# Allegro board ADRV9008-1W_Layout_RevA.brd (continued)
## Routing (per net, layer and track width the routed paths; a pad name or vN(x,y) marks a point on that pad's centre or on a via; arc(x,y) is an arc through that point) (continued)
OUT12_N: length 7.2
  BOTTOM w0.203: R431.1 80.57,63.93 80.58,63.92 ; 80.58,63.92 80.05,63.92 79.76,64.21 R433.1 ; 80.58,63.92 82.17,63.92 82.62,63.48 82.62,61.79 82.85,61.56 83.47,61.56 83.54,61.63 U401.29
OUT13: length 3.9
  BOTTOM w0.203: 81.75,59.71 83.63,59.71 83.72,59.63 U401.25 ; 81.75,59.71 R434.1 ; 81.75,59.71 81.06,59.71 R436.1
OUT13_N: length 3.9
  BOTTOM w0.203: 81.75,60.07 81.06,60.07 R435.1 ; 81.75,60.07 R434.2 ; 81.75,60.07 83.62,60.07 83.68,60.13 U401.26
PWRSUPPLYENABLE: length 111.8
  TOP w0.305: v2(79.68,19.06) 79.66,19.07 R902.1
  L8_SIG w0.394: v4(140.3,60.87) 142.31,60.87 143.58,59.6 143.58,49.9 145.04,48.45 145.04,33.69 143.58,32.24 143.58,22.2 143.19,21.81 142.66,21.81 142.31,21.46 142.31,20.87 141.98,20.54 141.39,20.54 138.89,18.04 127.56,18.04 127.02,18.58 123.59,18.58 122.42,19.75 121.66,19.75 121.39,19.48 120.1,19.48 120.09,19.47 119.55,19.47 119.54,19.48 116.34,19.48 115.71,20.11 98.31,20.11 97.31,19.11 79.73,19.11 v2(79.68,19.06)
  BOTTOM w0.394: v4(140.3,60.87) 139.74,60.31 P801.D1
REF_CLK_IN+: length 62.9
  BOTTOM w0.203: R436.2 79.47,59.71 78.74,59.71 ; 78.74,59.71 77.41,59.71 ; 78.74,59.71 C445.2 ; 77.41,59.71 77.09,59.71 arc(72.18,59.25) 67.44,57.88 arc(67.04,57.73) 66.63,57.6 66.64,57.6 arc(58.87,55.89) 50.94,55.27 50.94,55.27 arc(47.52,53.86) 46.11,50.44 46.11,45.64 arc(44.94,42.82) 42.12,41.65 38.29,41.65 arc(35.41,41.03) 33.1,39.2 arc(32.44,38) 32.21,36.64 32.21,35.86 ; 77.41,59.71 L401.1 ; 32.21,35.86 32.21,35.59 arc(32.24,35.42) C103.1 ; 32.21,35.86 R121.1
REF_CLK_IN-: length 63.5
  BOTTOM w0.203: R121.2 31.85,35.86 ; 31.85,35.86 31.85,36.64 arc(32.1,38.12) 32.83,39.43 arc(35.26,41.35) 38.29,42 42.12,42 arc(44.69,43.07) 45.75,45.64 45.75,50.44 arc(47.27,54.11) 50.94,55.62 arc(58.82,56.24) 66.54,57.94 arc(66.93,58.06) 67.31,58.21 arc(72.11,59.6) 77.09,60.07 77.41,60.07 ; 31.85,35.86 31.85,35.59 arc(31.81,35.42) C104.1 ; L401.2 77.41,60.07 ; 77.41,60.07 78.74,60.07 ; 78.74,60.07 79.47,60.07 R435.2 ; 78.74,60.07 C445.1
RESETB: length 120
  TOP w0.254: U101.J4 v1(35.64,31.68)
  TOP w0.394: TP803.1 128.99,48.07 129.42,48.5 R804.1
  L5_SIG w0.114: TP803.1 123.68,48.07 120.46,51.28 114.81,51.28 113.92,52.17 107.63,52.17 101.89,46.43 88.74,46.43 88.39,46.07 78.35,46.07 76.2,43.92 74.93,43.92 73.51,42.5 73.08,42.5 72.43,41.85 72.43,41.29 68.6,37.46 51.1,37.46 48.34,40.22 v5(40.9,40.22) 40.83,40.22 39.89,39.28 38.65,39.28 38.44,39.08 38.44,35.52 39.23,34.74 39.23,33.92 39.22,33.91 39.22,32.34 39,32.11 38.74,32.11 38.44,31.81 38.44,31.53 38.14,31.23 36.08,31.23 v1(35.64,31.68)
  BOTTOM w0.305: R110.2 40.16,38.61 40.9,39.35 v5(40.9,40.22)
RF_EXT_LO+: length 5.8
  TOP w0.203: U101.B8 v1(29.24,34.88)
  L10_SIG w0.254: v1(29.24,34.88) 29.24,34.58 28.89,34.24 27.98,34.24 27.83,34.09 25.47,34.09 v5(25.19,34.37)
  BOTTOM w0.203: C304.2 v5(25.19,34.37)
RF_EXT_LO-: length 5.8
  TOP w0.203: U101.B7 v1(29.24,33.28)
  L10_SIG w0.254: v5(25.19,33.45) 25.47,33.73 27.97,33.73 28.13,33.89 28.96,33.89 29.24,33.61 v1(29.24,33.28)
  BOTTOM w0.203: C305.2 v5(25.19,33.45)
RF_SYNTH_VTUNE: length 29.9
  TOP w0.203: C136.1 56.46,41.45 P104.5
  TOP w0.254: v5(34.04,35.68) U101.G9
  L7_SIG w0.114: v5(34.04,35.68) 34.42,36.06 34.42,38.13 34.83,38.54 34.98,38.54 35.18,38.74 35.18,38.9 35.56,39.28 42.99,39.28 44.9,41.19 46.99,41.19 48.33,42.52 51.95,42.52 52.13,42.34 53.24,42.34 53.48,42.58 55.18,42.58 P104.5
RX1_BAL+: length 3.3
  TOP w0.127: 18.86,38.89 T201.5
  TOP w0.203: 20.46,39.24 20.84,39.24 arc(21.2,39.17) R205.1 ; 20.46,39.24 19.85,39.24 arc(19.32,39.15) 18.86,38.89 arc(18.8,38.84) T201.5 ; 20.46,39.24 C204.1
RX1_BAL-: length 3.1
  TOP w0.203: 20.46,39.6 20.84,39.6 arc(21.2,39.67) R206.1 ; 20.46,39.6 C204.2 ; 20.46,39.6 19.84,39.6 arc(19.25,39.71) T201.4
RX1_ENABLE: length 37
  TOP w0.254: U101.M5 v1(38.04,31.68)
  TOP w0.305: R117.1 53.91,41.44 P104.7
  L5_SIG w0.114: P104.7 53.34,41.38 49.86,44.86 40.25,44.86 39.49,44.1 38.35,44.1 35.3,41.05 35.3,34.21 36.06,33.46 36.06,33.14 36.38,32.81 36.58,32.81 36.77,32.62 36.77,32.42 37.15,32.04 37.67,32.04 v1(38.04,31.68)
  BOTTOM w0.203: R839.1 P104.7
RX1_IN+: length 8.4
  TOP w0.203: U101.A9 28.7,35.41 arc(28.58,35.49) 28.44,35.52 arc(27.72,35.68) 27.12,36.11 25.16,38.34 arc(24.28,39) 23.21,39.24 ; 23.21,39.24 23.2,39.24 C207.1 ; 23.21,39.24 arc(23.12,39.24) 23.02,39.24 arc(22.56,39.17) R205.2
RX1_IN-: length 8.4
  TOP w0.203: 23.22,39.6 23.2,39.6 C207.2 ; 23.22,39.6 arc(23.11,39.6) 23.01,39.6 arc(22.55,39.66) R206.2 ; 23.22,39.6 arc(24.43,39.32) 25.42,38.58 27.39,36.35 arc(27.86,36) 28.44,35.88 28.5,35.88 arc(28.63,35.9) 28.74,35.98 U101.A10
RX1_UNBAL: length 2.2
  TOP w0.203: C248.1 13.11,40.1
  TOP w0.394: R202.2 C203.1 12.51,40.61 arc(12.65,40.48) 12.79,40.34 arc(12.95,40.22) 13.11,40.1
RX2_BAL+: length 3.6
  TOP w0.127: T202.5 19.12,29.57
  TOP w0.203: 20.46,29.75 19.85,29.75 arc(19.47,29.7) 19.12,29.57 arc(18.92,29.44) T202.5 ; 20.46,29.75 C211.1 ; 20.46,29.75 20.84,29.75 arc(21.2,29.67) R212.1
RX2_BAL-: length 3.1
  TOP w0.203: 20.46,30.1 19.84,30.1 arc(19.25,30.22) T202.4 ; 20.46,30.1 C211.2 ; 20.46,30.1 20.84,30.1 arc(21.2,30.17) R213.1
RX2_ENABLE: length 31.3
  TOP w0.254: U101.M7 v1(38.04,34.08)
  TOP w0.305: R116.1 53.91,38.77 P104.8
  L5_SIG w0.114: P104.8 52.58,40.11 50.93,40.11 48.19,42.85 43.44,42.85 43.05,42.45 38.6,42.45 36.84,40.69 36.84,35.53 37.08,35.29 37.37,35.29 37.66,35 37.66,34.46 v1(38.04,34.08)
  BOTTOM w0.203: R842.1 P104.8
RX2_IN+: length 7.6
  TOP w0.203: 23.21,29.74 23.02,29.75 arc(22.56,29.69) R212.2 ; 23.21,29.74 C214.1 ; 23.21,29.74 arc(23.98,29.85) 24.7,30.16 arc(25.8,30.85) 26.84,31.61 arc(27.61,32.06) 28.47,32.28 arc(28.69,32.23) U101.A5
RX2_IN-: length 7.7
  TOP w0.203: 23.19,30.1 23.02,30.1 arc(22.56,30.17) R213.2 ; 23.19,30.1 arc(23.2,30.17) C214.2 ; 23.19,30.1 arc(23.88,30.19) 24.52,30.47 arc(25.59,31.14) 26.62,31.89 arc(27.47,32.39) 28.44,32.63 arc(28.58,32.66) 28.7,32.74 U101.A6
RX2_UNBAL: length 4.1
  TOP w0.203: C249.1 12.96,30.56
  TOP w0.394: R209.2 C210.1 10.78,29.45 arc(11.1,30.23) 11.88,30.56 12.96,30.56
SERDOUT0+: length 3
  BOTTOM w0.203: P801.A2 143.55,58.42 arc(143.61,58.28) 143.75,58.22 145.7,58.22 arc(145.87,58.25) 146.02,58.35 C105.1
SERDOUT0-: length 3
  BOTTOM w0.203: P801.A3 143.55,57.66 arc(143.61,57.8) 143.75,57.86 145.7,57.86 arc(145.87,57.83) 146.02,57.73 C106.1
SERDOUT1+: length 3
  BOTTOM w0.203: P801.A6 143.55,53.34 arc(143.61,53.2) 143.75,53.14 145.7,53.14 arc(145.87,53.17) 146.02,53.27 C107.1
SERDOUT1-: length 3
  BOTTOM w0.203: C108.1 146.02,52.65 arc(145.87,52.75) 145.7,52.78 143.75,52.78 arc(143.61,52.72) 143.55,52.58 P801.A7
SERDOUT2+: length 1.4
  TOP w0.203: v4(141.67,52.95) 141.67,52.93 C109.1
  BOTTOM w0.203: v4(141.67,52.95) 141.66,52.95 P801.C6
SERDOUT2-: length 1.4
  TOP w0.203: v4(141.64,51.69) C110.1
  BOTTOM w0.203: v4(141.64,51.69) P801.C7
SERDOUT3+: length 3
  BOTTOM w0.203: P801.A10 143.55,48.26 arc(143.61,48.12) 143.75,48.06 145.7,48.06 arc(145.87,48.09) 146.02,48.19 C111.1
SERDOUT3-: length 3
  BOTTOM w0.203: P801.A11 143.55,47.5 arc(143.61,47.64) 143.75,47.7 145.7,47.7 arc(145.87,47.67) 146.02,47.57 C112.1
SPI_CLK: length 112.9
  TOP w0.254: U403.3 120.14,47.94 121.68,46.4 121.68,44.26 TP805.1 ; U101.K9 v1(36.44,35.68)
  TOP w0.305: R806.1 131.17,43.47 129.64,41.95 121.6,41.95 TP805.1
  L7_SIG w0.114: v3(89.47,45.89) 89.79,46.2 100.9,46.2 105.16,41.95 119.37,41.95 TP805.1
  L8_SIG w0.114: v1(36.44,35.68) 36.69,35.68 37.08,35.29 41.54,35.29 43.18,36.93 45.21,36.93 51.69,43.41 70.36,43.41 72.39,45.44 77.09,45.44 77.72,46.07 89.29,46.07 v3(89.47,45.89)
SPI_CLK_9528: length 43.5
  TOP w0.203: U403.12 v2(120.14,53.63)
  L7_SIG w0.114: v2(120.14,53.63) 98.81,53.63 98.43,54.01 87.82,54.01 83.76,58.08 82.42,58.08 v2(82.21,58.29)
  BOTTOM w0.254: U401.22 83.47,58.13 83.38,58.04 82.46,58.04 v2(82.21,58.29)
SPI_CS0: length 119.8
  TOP w0.254: U101.K10 v1(36.44,36.48) ; v4(139.1,42.87) 138.89,42.87 138.55,42.53 R832.2 R846.1 ; TP816.1 119.9,45.99 118.65,47.24 117.33,47.24 116.71,47.86 U402.7
  L7_SIG w0.114: TP816.1 119.34,44.84 116.88,44.84 115,42.97 105.67,42.97 101.6,47.03 96.52,47.03 96.01,47.54 v3(88.2,47.54)
  L8_SIG w0.114: v3(88.2,47.54) 72.08,47.54 68.84,44.3 48.96,44.3 44.88,40.22 43.42,40.22 40.43,37.22 40.36,37.22 40.01,36.88 36.84,36.88 v1(36.44,36.48)
  L8_SIG w0.254: v4(139.1,42.87) 138.49,43.48 124.64,43.48 123.63,44.49 121.98,44.49 TP816.1
SPI_CS1: length 34.8
  TOP w0.254: 121.44,50.48 U403.5
  TOP w0.305: U402.1 120.6,51.32 121.44,50.48 122.03,51.08 123.99,51.08 TP815.1 130.59,49.7 130.74,49.86 134.53,49.86 135.89,48.49 135.89,47.6 136.27,47.22 136.74,47.22 137.12,46.84 137.12,40.05 137.5,39.67 138.21,39.67 138.55,40.01 R833.2 R847.1
SPI_CS_9528: length 46.6
  TOP w0.203: U403.10 v2(121.44,53.63)
  L7_SIG w0.114: v2(81.7,57.55) 83.33,57.55 87.31,53.58 87.4,53.58 87.6,53.38 98.05,53.38 98.68,52.74 103.63,52.74 104.14,52.24 105.03,52.24 105.54,52.74 114.81,52.74 115.06,53 120.8,53 v2(121.44,53.63)
  BOTTOM w0.254: U401.21 83.78,57.63 83.69,57.63 83.62,57.55 v2(81.7,57.55)
SPI_DIN: length 114.2
  TOP w0.254: U101.J9 v1(35.64,35.68) ; U403.4 120.79,48.18 123,45.96 TP806.1
  TOP w0.305: TP806.1 125.39,43.98 129.45,43.98 130.14,44.67 R807.1
  L7_SIG w0.114: TP806.1 122.03,47.33 117.4,47.33 113.93,43.86 106.18,43.86 102.24,47.8 96.97,47.8 96.58,48.19 85.49,48.19 v1(84.01,46.71)
  L8_SIG w0.114: v1(84.01,46.71) 84,46.7 72.45,46.7 69.6,43.85 49.98,43.85 44.33,38.2 43.06,38.2 41.33,36.48 40.85,36.48 40.43,36.06 36.03,36.06 v1(35.64,35.68)
SPI_DIN_9528: length 42.5
  TOP w0.203: U403.11 v2(120.79,56.55)
  L7_SIG w0.114: v2(120.79,56.55) 119.01,54.78 109.35,54.78 109.1,55.03 94.62,55.03 93.72,55.93 87.88,55.93 85.09,58.71 83.36,58.71 v2(83.28,58.63)
  BOTTOM w0.254: U401.23 83.68,58.63 v2(83.28,58.63)
SPI_DOUT: length 31.1
  TOP w0.203: 117.59,45.99 TP811.1 ; 116.2,48.63 U402.6
  TOP w0.254: U402.3 116.21,48.65 116.19,48.62 116.19,47.39 118.66,44.92 118.66,42.26 119.6,41.31 132.84,41.31 133.69,42.16 134.13,42.16 134.53,42.56 134.53,42.81 135.26,43.54 135.51,43.54 136.06,44.09 136.06,45.94 R845.1
SPI_DOUT_9528: length 38.8
  TOP w0.203: R453.2 114.11,55.92 TP400.1
  L7_SIG w0.114: v2(82.56,58.95) 83.01,59.4 86.06,59.4 86.49,58.97 93.73,58.97 96.78,55.92 TP400.1
  BOTTOM w0.254: v2(82.56,58.95) 82.83,59.21 83.59,59.21 83.67,59.13 83.81,59.13 U401.24
SPI_DOUT_DUT: length 91.5
  TOP w0.254: U101.J10 v1(35.64,36.48) ; R454.2 116.07,44.56 TP401.1
  L7_SIG w0.097: 39.49,33.69 39.89,33.69
  L7_SIG w0.114: 39.49,33.69 37.95,33.69 37.63,34.01 37.63,34.24 37.4,34.46 37.1,34.46 36.07,35.5 36.07,36.04 v1(35.64,36.48) ; v2(79.64,37.38) 78.43,37.38 77.03,35.98 77.03,35.84 74.6,33.41 45.85,33.41 45.3,33.96 44.71,33.96 44.45,34.22 43.2,34.22 42.67,33.69 39.89,33.69
  BOTTOM w0.394: TP401.1 111.83,37.38 v2(79.64,37.38)
STATUS_0: length 3.2
  TOP w0.203: R444.1 v2(95.57,65.95)
  BOTTOM w0.254: U401.55 94.75,65.13 v2(95.57,65.95) ; R444.1 95.57,66.59
  BOTTOM w0.394: 95.57,66.59 v2(95.57,65.95)
STATUS_1: length 4.5
  TOP w0.203: v2(96.64,65.95) 96.64,66.69 R445.1
  BOTTOM w0.254: v2(96.64,65.95) 96.52,65.95 95.2,64.63 U401.56
  BOTTOM w0.394: v2(96.64,65.95) R443.1
SYNCINB0+: length 148.6
  TOP w0.203: v4(137.83,49.15) 137.81,49.13 R820.1
  TOP w0.254: U101.M4 v1(38.04,30.88)
  L7_SIG w0.091: v4(137.83,49.15) 138.29,48.69 143.14,48.69 143.75,48.07 143.75,29.73 141.97,27.95 141.36,27.95 139.91,26.5 139.91,23.39 137.78,21.26 136.77,21.26 132.45,16.94 127.77,16.94 127.14,16.3 ; 127.14,16.3 126.63,15.79 119.66,15.79 116.24,19.22 113.19,19.22 111.79,20.62 110.14,20.62 105.19,25.57 60.57,25.57 59.68,24.68 49.14,24.68 46.23,27.6 44.96,27.6 44.57,27.98 40.77,27.98 39.84,28.92 37.93,28.92 37.71,29.15 37.71,30.21 38.04,30.55 v1(38.04,30.88) ; 127.14,16.3 TP809.1
SYNCINB0-: length 147.4
  TOP w0.203: R821.1 137.81,47.86 v4(137.83,47.88)
  TOP w0.254: U101.M3 v1(38.04,30.08)
  L7_SIG w0.091: 126.96,16.48 127.67,17.19 132.34,17.19 136.66,21.51 137.68,21.51 139.66,23.49 139.66,26.61 141.26,28.21 141.87,28.21 143.5,29.84 143.5,47.97 143.03,48.44 138.19,48.44 137.93,48.69 137.8,48.69 137.42,48.31 137.42,48 137.55,47.88 137.83,47.88 v4(137.83,47.88) ; 126.96,16.48 126.96,16.48 126.52,16.05 119.77,16.05 116.34,19.48 113.29,19.48 111.9,20.87 110.25,20.87 105.29,25.83 60.46,25.83 59.57,24.94 49.25,24.94 46.34,27.85 45.07,27.85 44.68,28.24 40.87,28.24 40.09,29.02 40.09,29.3 39.76,29.62 38.14,29.62 38.04,29.72 v1(38.04,30.08) ; 126.96,16.48 TP810.1
SYNCINB1+: length 107.9
  TOP w0.203: v4(134.02,26.29) 134.46,26.73 R828.1
  TOP w0.254: U101.L4 v1(37.24,30.88)
  L7_SIG w0.091: 116.02,21.44 116.66,22.08 119.06,24.49 120.63,24.49 121.39,23.73 122.87,23.73 123.26,24.11 124.38,24.11 125.01,23.47 127.38,23.47 128.4,24.49 131.89,24.49 133.19,25.78 133.93,25.78 134.02,25.87 v4(134.02,26.29) ; 116.02,21.44 116.02,21.58 TP812.1 ; 116.02,21.44 115.71,21.13 114.54,21.13 113.4,22.27 111.01,22.27 109.02,24.26 108.88,24.26 105.28,27.86 49.54,27.86 48.4,29 46.08,29 44.05,31.03 40.01,31.03 39.77,31.28 38.62,31.28 38.36,31.54 38.36,31.81 38.17,32 37.9,32 37.66,31.76 37.66,31.33 37.33,30.99 37.33,30.96 v1(37.24,30.88)
SYNCINB1-: length 107.8
  TOP w0.203: v4(134.02,25.02) 134.47,25.47 R829.1
  TOP w0.254: U101.L3 v1(37.24,30.08)
  L7_SIG w0.091: 116.84,21.9 117.55,21.19 TP813.1 ; 116.84,21.9 115.81,20.87 114.44,20.87 113.29,22.02 110.9,22.02 108.92,24 108.78,24 105.18,27.61 49.43,27.61 48.29,28.75 45.98,28.75 43.95,30.78 40.01,30.78 39.76,30.53 38.73,30.53 38.36,30.89 38.36,31.01 38.17,31.2 37.89,31.2 37.58,30.89 37.58,30.76 37.56,30.74 37.56,30.74 37.24,30.42 v1(37.24,30.08) ; 116.84,21.9 119.17,24.23 120.52,24.23 121.29,23.47 122.98,23.47 123.36,23.85 124.27,23.85 124.91,23.22 127.49,23.22 128.5,24.23 132,24.23 133.29,25.53 133.77,25.53 134.02,25.28 v4(134.02,25.02)
SYSREF_CLK_IN+: length 2.4
  BOTTOM w0.203: R451.2 96.2,57.56 95.11,57.56 95.04,57.63 U401.70
SYSREF_CLK_IN-: length 2.4
  BOTTOM w0.203: U401.71 95.04,57.13 95.11,57.2 96.02,57.2 96.03,57.19 96.15,57.19 R452.2
SYSREF_IN+: length 89.9
  TOP w0.254: U101.K3 v1(36.44,30.08)
  L7_SIG w0.091: v2(73.88,63.33) 74.08,63.54 76.46,63.54 77.98,62.02 77.98,61 80.27,58.71 80.27,55.92 82.25,53.93 82.25,49.24 80.4,47.39 67.05,47.39 64.28,44.62 46.12,44.62 43.84,42.33 36.47,42.33 32.66,38.52 32.66,37.63 31.86,36.83 31.86,36.02 32.51,35.37 32.51,34.58 32.91,34.19 32.91,33.94 33.1,33.75 33.35,33.75 34.51,32.59 34.51,31.52 34.75,31.28 34.95,31.28 35.65,30.58 36.01,30.58 36.44,30.15 v1(36.44,30.08)
  BOTTOM w0.203: v2(73.88,63.33) 74.1,63.56 77.64,63.56 77.89,63.32 R432.2
SYSREF_IN-: length 89.8
  TOP w0.254: U101.K4 v1(36.44,30.88)
  L7_SIG w0.091: v2(73.88,64.15) 74.23,63.79 76.56,63.79 78.23,62.12 78.23,61.11 80.52,58.82 80.52,56.03 82.51,54.04 82.51,49.14 80.5,47.13 67.15,47.13 64.38,44.36 46.23,44.36 43.94,42.08 36.58,42.08 32.91,38.41 32.91,37.52 32.11,36.72 32.11,36.13 32.77,35.47 32.77,34.69 33.06,34.4 33.37,34.4 33.56,34.21 33.56,33.89 34.66,32.8 34.67,32.8 34.97,32.8 35.16,32.61 35.16,31.43 35.76,30.83 36.39,30.83 v1(36.44,30.88)
  BOTTOM w0.203: R433.2 77.89,64.21 77.6,63.92 74.1,63.92 v2(73.88,64.15)
TEST: length 176.3
  TOP w0.203: R836.1 135.38,40.87 137.79,38.46 140.98,38.46
  TOP w0.254: U101.J6 v1(35.64,33.28)
  TOP w0.394: R112.1 R111.2 143.55,11.65 144.95,13.05 144.95,20.46 143.61,21.8 143.61,28.09 142.12,29.57 142.12,30.63 140.98,31.78 140.98,38.46 142.34,39.82 142.34,44.65 v4(141.67,45.32)
  L7_SIG w0.114: v4(141.67,45.32) 140.9,46.09 133.67,46.09 133.31,46.45 126.8,46.45 124.46,44.11 TP817.1 122.62,42.27 121.67,41.31 104.4,41.31 100.26,45.46 91.39,45.46 91.06,45.12 85.6,45.12 82.49,42.01 82.49,41.06 81.54,40.11 80.71,40.11 79.95,39.35 79.95,38.27 80.27,37.95 80.27,36.74 78.97,35.45 78.97,34.16 76.11,31.3 53.85,31.3 53.22,31.93 51.68,31.93 51.55,31.8 45.84,31.8 44.7,32.94 38.7,32.94 38.44,33.19 37.73,33.19 37.47,32.94 35.97,32.94 v1(35.64,33.28)
UNNAMED_2_ADRV90081_I127_RBIAS: length 2.5
  TOP w0.203: U101.C14 28.89,40.82 R101.1
UNNAMED_2_ADRV90081_I127_SERDOU: length 126.7
  TOP w0.203: U101.P4 v1(39.56,30.95)
  L10_SIG w0.091: 147.32,52.58 arc(147.2,52.79) 146.96,52.87 146.95,52.87 arc(146.7,52.82) 146.48,52.68 146.42,52.61 arc(144.51,49.79) 143.84,46.44 143.84,37.96 arc(143.15,36.29) 141.48,35.6 141.47,35.6 arc(140.48,35.47) 139.6,35.02 arc(138.81,34.6) 137.92,34.46 133.35,34.46 arc(130.72,34.01) 128.49,32.55 arc(120.75,27.38) 111.63,25.57 63.41,25.57 arc(58.18,26.22) 53.25,28.11 arc(47.34,30.36) 41.05,31.13 39.98,31.13 arc(39.75,31.08) v1(39.56,30.95)
  BOTTOM w0.203: C108.2 147.32,52.58
UNNAMED_2_ADRV90081_I127_VDDA1P: length 1.7
  TOP w0.203: v5(30.08,36.48) 30.84,36.48
  TOP w0.254: 30.84,36.48 U101.D10
  BOTTOM w0.305: v5(30.08,36.48) 30.08,36.82 30.1,36.84 30.1,36.87
  BOTTOM w0.394: C137.1 30.1,36.87
UNNAMED_2_ADRV90081_I127_VDDA_1: length 1.2
  TOP w0.254: v4(38.04,28.48) U101.M1
  BOTTOM w0.305: 37.96,28.55 v4(38.04,28.48)
  BOTTOM w0.394: 37.96,28.55 37.66,28.86 C101.1
UNNAMED_2_ADRV90081_I127_VDDA_2: length 0.9
  TOP w0.254: v4(30.04,33.28) U101.C7
  BOTTOM w0.203: v4(30.04,33.28) 30.06,33.25 C102.1
UNNAMED_2_CAP_I88_N2: length 1.2
  TOP w0.203: U101.E7 v5(32.44,34.08)
  BOTTOM w0.203: C103.2 32.34,34.3 arc(32.37,34.18) v5(32.44,34.08)
UNNAMED_2_CAP_I89_N2: length 1.2
  TOP w0.203: U101.E8 v5(31.64,34.08)
  BOTTOM w0.203: C104.2 31.71,34.25 arc(31.69,34.16) v5(31.64,34.08)
UNNAMED_2_CAP_I91_N2: length 123.6
  TOP w0.203: U101.P7 v1(39.56,33.35)
  L10_SIG w0.091: 147.32,58.42 arc(147.19,58.23) 146.98,58.15 146.7,58.15 arc(144.61,57.64) 143.04,56.17 arc(143.03,56.16) 143.02,56.15 arc(142.65,55.58) 142.2,55.07 141.23,54.09 arc(140.79,53.8) 140.27,53.7 arc(139.75,53.59) 139.3,53.29 137.45,51.44 arc(137.21,51.08) 137.12,50.66 137.12,41.45 arc(136.63,40.26) 135.45,39.77 133.77,39.77 arc(126.65,38.75) 120.11,35.77 arc(116.05,33.93) 111.63,33.3 55.5,33.3 arc(52.96,33.34) 50.42,33.29 arc(45.35,33.13) 40.28,33.08 40.05,33.08 arc(39.77,33.15) v1(39.56,33.35)
  BOTTOM w0.203: C105.2 147.32,58.42
UNNAMED_2_CAP_I92_N2: length 123.6
  TOP w0.203: U101.P6 v1(39.56,32.55)
  L10_SIG w0.091: 147.32,57.66 arc(147.2,57.84) 146.99,57.9 146.98,57.9 146.69,57.9 arc(144.73,57.42) 143.25,56.04 arc(143.25,56.03) 143.24,56.02 arc(142.87,55.46) 142.44,54.95 142.44,54.95 141.84,54.35 141.41,53.91 arc(140.89,53.57) 140.27,53.44 arc(139.84,53.36) 139.48,53.11 138.87,52.5 137.63,51.26 arc(137.44,50.98) 137.38,50.66 137.38,41.45 arc(136.81,40.08) 135.45,39.52 133.77,39.52 arc(126.72,38.5) 120.25,35.56 arc(116.12,33.69) 111.63,33.05 55.49,33.05 arc(52.96,33.09) 50.43,33.03 arc(45.36,32.88) 40.28,32.83 40.05,32.83 arc(39.77,32.75) v1(39.56,32.55)
  BOTTOM w0.203: C106.2 147.32,57.66
UNNAMED_2_CAP_I94_N2: length 126.7
  TOP w0.203: U101.P5 v1(39.7,31.62)
  L10_SIG w0.091: v1(39.7,31.62) 39.8,31.53 arc(39.96,31.42) 40.15,31.38 41.05,31.38 arc(47.4,30.61) 53.37,28.33 arc(58.24,26.47) 63.41,25.82 111.63,25.82 arc(120.66,27.62) 128.31,32.73 arc(130.63,34.25) 133.36,34.71 137.92,34.71 arc(138.73,34.84) 139.45,35.22 arc(140.41,35.71) 141.48,35.85 arc(142.97,36.47) 143.59,37.96 143.59,46.44 arc(144.28,49.89) 146.24,52.79 146.3,52.85 arc(146.6,53.05) 146.95,53.12 arc(147.16,53.19) 147.32,53.34
  BOTTOM w0.203: C107.2 147.32,53.34
UNNAMED_2_CAP_I95_N2: length 127.4
  TOP w0.254: v1(38.84,30.08) U101.N3
  L10_SIG w0.091: v1(38.84,30.08) arc(39.06,30.28) 39.36,30.35 40.95,30.35 arc(45.45,29.63) 49.49,27.55 arc(55.22,24.63) 61.58,23.7 111.63,23.7 arc(120.53,25.31) 128.3,29.94 arc(130.75,31.39) 133.56,31.86 143.03,31.86 arc(144.54,32.49) 145.16,34 145.16,45.57 arc(145.69,47.01) 147.02,47.77 arc(147.24,47.71) 147.32,47.5
  BOTTOM w0.203: C112.2 147.32,47.5
UNNAMED_2_CAP_I96_N2: length 119.9
  TOP w0.203: C109.2 v1(142.91,51.69)
  TOP w0.254: v1(38.84,32.48) U101.N6
  L10_SIG w0.091: v1(38.84,32.48) arc(38.84,32.29) 39,32.2 41.89,32.2 arc(47.07,31.88) 52.16,30.92 arc(57.67,29.89) 63.26,29.56 111.63,29.56 arc(117.94,30.61) 123.57,33.64 arc(128.49,36.29) 134,37.21 136.94,37.21 arc(138.78,37.51) 140.42,38.37 arc(141.69,39.88) 142.15,41.8 142.15,48.76 arc(142.11,49.17) 141.98,49.56 141.77,50.03 arc(141.7,50.27) 141.68,50.52 arc(141.92,51.07) 142.49,51.26 arc(142.81,51.37) v1(142.91,51.69)
UNNAMED_2_CAP_I97_N2: length 119.9
  TOP w0.203: C110.2 v1(142.91,50.42)
  TOP w0.254: v1(38.84,31.68) U101.N5
  L10_SIG w0.091: v1(142.91,50.42) arc(142.82,50.81) 142.47,51.01 arc(142.09,50.88) 141.93,50.52 arc(141.95,50.32) 142.01,50.13 142.21,49.66 arc(142.36,49.22) 142.4,48.76 142.4,41.8 arc(141.92,39.76) 140.58,38.16 arc(138.86,37.27) 136.95,36.95 134,36.95 arc(128.57,36.05) 123.73,33.44 arc(118.02,30.37) 111.63,29.31 63.26,29.31 arc(57.63,29.64) 52.1,30.68 arc(47.03,31.63) 41.89,31.95 39.25,31.95 arc(39.01,31.87) v1(38.84,31.68)
UNNAMED_2_CAP_I98_N2: length 127.4
  TOP w0.254: v1(38.84,30.88) U101.N4
  L10_SIG w0.091: 147.32,48.26 arc(147.17,48.1) 146.97,48.02 arc(145.49,47.17) 144.91,45.57 144.91,34 arc(144.36,32.67) 143.03,32.12 133.57,32.12 arc(130.67,31.63) 128.13,30.14 arc(120.44,25.55) 111.63,23.95 61.58,23.95 arc(55.3,24.87) 49.64,27.75 arc(45.52,29.87) 40.95,30.6 39.05,30.6 arc(38.88,30.69) v1(38.84,30.88)
  BOTTOM w0.203: C111.2 147.32,48.26
UNNAMED_2_ICS25FL208K_I27_HOLDN: length 2.2
  BOTTOM w0.203: R119.2 44.33,60.05
UNNAMED_2_ICS25FL208K_I27_WPN: length 2.3
  BOTTOM w0.203: R120.2 U102.3
UNNAMED_3_CAP_I159_N1: length 11.3
  TOP w0.305: R202.1 11.07,42.09
  TOP w0.394: J201.1 2.55,46.48 arc(6.36,45.72) 9.6,43.56 C201.1 11.07,42.09
UNNAMED_3_CAP_I180_N1: length 12.9
  TOP w0.394: R209.1 C208.1 arc(9.56,23.85) 6.55,22.61 J202.1
UNNAMED_3_CAP_I241_N2: length 2.7
  TOP w0.305: 13.46,38.39 13.39,38.33
  TOP w0.457: 13.39,38.33 C240.2
  TOP w0.508: 13.46,38.39 13.74,38.39 13.75,38.4 C241.2 14.42,38.78 T201.2
UNNAMED_3_CAP_I245_N1: length 2.7
  TOP w0.508: C243.1 13.54,28.81 13.64,28.91 C242.2 14.42,29.29 T202.2
UNNAMED_3_CAP_I256_N2: length 1.1
  TOP w0.203: 14.42,40.05 14.92,40.05 ; C248.2 13.95,40.05
  TOP w0.394: 13.95,40.05 14.42,40.05 ; 14.6,40.06 14.59,40.05
UNNAMED_3_CAP_I257_N2: length 1.1
  TOP w0.203: C249.2 13.95,30.56 ; 14.42,30.56 14.92,30.56
  TOP w0.394: 14.6,30.56 14.6,30.56 ; 13.95,30.56 14.42,30.56
UNNAMED_4_CAP_I166_N1: length 4.6
  BOTTOM w0.203: R405.2 96.02,50.42 ; 96.02,50.42 96.83,50.42 R404.2 97.46,49.79 98.01,49.79 98.48,49.32 T401.3 ; 96.02,50.42 95.2,50.42 C405.1
UNNAMED_4_CAP_I168_N1: length 6.4
  BOTTOM w0.394: C401.1 R401.2 107.27,47.87 J401.1
UNNAMED_4_CAP_I168_N2: length 1.6
  BOTTOM w0.394: C401.2 T401.4
UNNAMED_4_CAP_I177_N1: length 4.6
  BOTTOM w0.203: C403.1 95.2,50.77 96.02,50.77 ; R405.1 96.02,50.77 ; 96.02,50.77 96.85,50.77 R403.1 97.49,51.42 97.99,51.42 98.43,51.86 T401.1
UNNAMED_4_CAP_I184_N1: length 61.4
  BOTTOM w0.203: R417.2 R413.1 108.27,60.61 107.45,61.44 105.03,61.44 103.54,59.96 103.54,56.53 106.9,53.17 113,53.17 115.6,50.57 115.6,45.41 113.65,43.46 100.87,43.46 96.93,47.39 89.65,47.39 88.43,48.61 88.43,49.34 88.76,49.67 C409.1
UNNAMED_4_CAP_I192_N2: length 1.2
  BOTTOM w0.203: R439.1 91.56,53.74 C415.2
UNNAMED_4_CAP_I292_N2: length 2.5
  TOP w0.203: C411.2 105.78,63.08 105.78,62.09 105.98,61.89 J405.1
UNNAMED_4_CAP_I294_N2: length 2.5
  TOP w0.203: J404.1 105.22,61.89 105.42,62.09 105.42,63.08 C410.2
UNNAMED_4_CAP_I303_N2: length 1.7
  TOP w0.203: C413.2 79.19,64.18 J407.1
UNNAMED_4_CAP_I304_N2: length 1.7
  TOP w0.203: J406.1 78.17,64.18 C412.2
UNNAMED_4_CAP_I329_N1: length 3.2
  TOP w0.203: R449.2 97.36,57 R450.2 95.84,56.44 v2(95.84,55.87)
  BOTTOM w0.203: C420.1 v2(95.84,55.87)
UNNAMED_4_CAP_I330_N1: length 3.3
  TOP w0.203: v2(95.84,58.83) 95.84,58.19 R450.1 97.36,57.63 R448.2
  BOTTOM w0.203: C419.1 v2(95.84,58.83)
UNNAMED_4_CMOSNC7WV125K8X_I27_1: length 3.6
  TOP w0.203: 115.71,48.39 U402.5
  TOP w0.254: R454.1 115.33,47.67 115.71,48.06 115.71,48.39
UNNAMED_4_CMOSNC7WV125K8X_I279_: length 1.4
  TOP w0.254: R453.1 116.72,52.2 116.71,52.19 U402.2
UNNAMED_4_CNBNC3P_I148_CNTR: length 10.5
  TOP w0.203: v2(79.05,58.41) 79.02,58.41 79.02,59.51 78.81,59.71 75.16,59.71 74.33,58.88 74.33,56.7 74.48,56.55 J411.1
  BOTTOM w0.203: R438.2 v2(79.05,58.41)
UNNAMED_4_CNBNC3P_I248_CNTR: length 10.5
  TOP w0.203: v2(79.02,61.37) 79.02,60.27 78.81,60.07 75.01,60.07 73.98,59.03 73.98,56.82 73.71,56.55 J410.1
  BOTTOM w0.203: R437.2 v2(79.02,61.37)
UNNAMED_4_CNBNC3P_I306_CNTR: length 1.7
  TOP w0.203: R430.2 68.39,64.18 J409.1
UNNAMED_4_CNBNC3P_I308_CNTR: length 1.7
  TOP w0.203: R429.2 69.41,64.18 J408.1
UNNAMED_4_CNBNC3P_I318_CNTR: length 11.7
  TOP w0.203: J403.1 106.68,55.79 105.96,56.51 105.96,57.53 104.29,59.2 101.88,59.2 100.53,60.54 99.76,60.54 99.56,60.75 v2(99.56,61.88)
  BOTTOM w0.203: R422.1 v2(99.56,61.88)
UNNAMED_4_CNBNC3P_I321_CNTR: length 11.7
  TOP w0.203: v2(99.52,58.85) 99.56,58.85 99.56,59.98 99.76,60.19 100.38,60.19 101.73,58.84 104.14,58.84 105.61,57.38 105.61,56.11 105.29,55.79 J402.1
  BOTTOM w0.203: R421.1 v2(99.52,58.85)
UNNAMED_4_CNBNC3P_I324_CNTR: length 9.5
  TOP w0.203: R448.1 99.91,57.82 100.32,57.41 100.32,51.17 100.52,50.97 100.97,50.97 J412.1
UNNAMED_4_CNBNC3P_I325_CNTR: length 9.5
  TOP w0.203: J413.1 99.57,50.59 99.96,50.98 99.96,57.27 99.76,57.47 99.34,57.47 99.19,57.32 99.19,56.94 99.05,56.79 98.56,56.79 R449.1
UNNAMED_4_CNTP1P_I73_N1: length 11.5
  TOP w0.203: TP403.1 99.71,67.72 R444.2
  BOTTOM w0.203: U405.1 101.31,66.12 TP403.1
UNNAMED_4_CNTP1P_I74_N1: length 9.5
  TOP w0.203: TP402.1 101.98,66.21 98.3,66.21 97.79,66.71 R445.2
  BOTTOM w0.305: TP402.1 106.37,67.48 U405.3
UNNAMED_4_DIOLED_I333_P: length 1.5
  TOP w0.203: R446.2 DS401.A
UNNAMED_4_DIOLED_I334_P: length 1.5
  TOP w0.203: R447.2 DS402.A
UNNAMED_4_NC7WZ17P6X_I76_Y1: length 2.8
  TOP w0.203: R446.1 v2(109.74,67.22)
  BOTTOM w0.203: U405.6 108.88,66.12 109.74,66.98 v2(109.74,67.22)
UNNAMED_4_NC7WZ17P6X_I76_Y2: length 1.9
  TOP w0.203: R447.1 v2(109.1,68.37)
  BOTTOM w0.203: U405.4 109.1,68.19 v2(109.1,68.37)
UNNAMED_4_RES_I165_N2: length 61.4
  BOTTOM w0.203: R411.1 87.74,49.67 88.07,49.34 88.07,48.46 89.5,47.04 96.78,47.04 100.72,43.1 113.8,43.1 115.96,45.26 115.96,50.71 113.14,53.53 107.05,53.53 103.9,56.68 103.9,58.23 104.34,58.67 105.64,58.67 106.67,57.65 107.62,57.65 107.96,57.98 107.96,59.13 R412.2 R410.2
UNNAMED_4_RES_I268_N2: length 1.6
  BOTTOM w0.394: T401.5 R402.2
UNNAMED_5_CNTP1P_I268_N1: length 2
  BOTTOM w0.508: 23.62,63.03 TP604.1 22.61,64.05
UNNAMED_5_RES_I164_N2: length 3.3
  BOTTOM w0.762: 6.99,47.66 R608.2 ; R613.1 7.75,46.52 7.64,46.52 7.62,46.54
  BOTTOM w1.016: 7.62,46.54 7.62,47.41 ; 7.62,47.41 7.24,47.41 6.99,47.66 ; 7.62,47.41 TP610.1
UNNAMED_5_RES_I174_N2: length 5.8
  BOTTOM w0.394: R604.2 TP606.1 R612.1
UNNAMED_7_CAP_I11_N2: length 1.5
  TOP w0.203: C802.2 v4(139.12,55.52)
  BOTTOM w0.203: v4(139.12,55.52) 139.74,54.9 P801.D5
UNNAMED_7_CAP_I12_N2: length 1.5
  TOP w0.203: C801.2 140.39,55.5 v4(140.36,55.47)
  BOTTOM w0.203: v4(140.36,55.47) 139.74,56.1 P801.D4
UNNAMED_7_CAP_I157_N2: length 25.5
  TOP w0.203: C803.2 140.84,55.28 140.84,55.27 140.56,54.99 140.56,54.99 140.46,54.89 140.29,54.89 140.05,54.65 140.05,54.34 140.55,53.84 143.21,53.84 143.8,53.25 143.8,38.56 142.52,37.27 142.52,35.58 v4(142.91,35.18)
  BOTTOM w0.203: v4(142.91,35.18) P801.B20
UNNAMED_7_CAP_I158_N2: length 25.5
  TOP w0.203: v4(141.67,35.14) 142.16,35.63 142.16,37.42 143.45,38.71 143.45,53.11 143.07,53.49 140.4,53.49 139.67,54.22 139.67,54.27 139.59,54.35 139.59,54.43 139.3,54.71 139.23,54.71 C804.2
  BOTTOM w0.203: v4(141.67,35.14) 142.27,34.54 P801.B21
UNNAMED_7_CN400PAK_I2_N8: length 1.6
  TOP w0.203: v4(140.39,51.71) 140.27,51.6 R834.2
  BOTTOM w0.203: v4(140.39,51.71) 140.39,51.7 P801.D8
UNNAMED_7_CN400PAK_I2_N9: length 1.2
  TOP w0.203: R835.2 139.13,49.18 v4(139.1,49.15)
  BOTTOM w0.203: P801.D9 v4(139.1,49.15)
UNNAMED_7_CN400PAK_I2_N14: length 1.5
  TOP w0.305: R846.2 140.38,42.79 v4(140.37,42.8)
  BOTTOM w0.203: P801.D14 v4(140.37,42.8)
UNNAMED_7_CN400PAK_I2_N15: length 1.5
  TOP w0.305: v4(140.37,41.53) 140.38,41.52 R847.2
  BOTTOM w0.203: P801.D15 v4(140.37,41.53)
UNNAMED_7_CN400PAK_I2_N18: length 90.2
  L8_SIG w0.114: v4(139.1,38.99) 138.23,38.99 136.28,40.94 123.71,40.94 123.7,40.95 123.27,40.95 123.26,40.94 107.96,40.94 103.39,45.51 90.74,45.51 89.85,44.62 87.63,44.62 87.51,44.74 78.49,44.74 77.6,43.85 72.52,43.85 71,42.33 69.41,42.33 69.03,41.95 v2(63.18,41.95)
  BOTTOM w0.203: R839.2 62.28,42.85 v2(63.18,41.95) ; P801.D18 v4(139.1,38.99)
UNNAMED_7_CN400PAK_I27_N10: length 1.2
  TOP w0.203: v4(140.37,47.88) 140.4,47.91 R816.2
  BOTTOM w0.203: P801.C10 v4(140.37,47.88)
UNNAMED_7_CN400PAK_I27_N11: length 1.2
  TOP w0.203: R817.2 141.61,47.92 v4(141.64,47.88)
  BOTTOM w0.203: P801.C11 v4(141.64,47.88)
UNNAMED_7_CN400PAK_I27_N19: length 95.3
  L8_SIG w0.114: v2(64.07,40.04) 76.52,40.04 77.41,40.93 77.41,41.82 78.36,42.78 84.97,42.78 85.45,43.26 90.53,43.26 91,43.73 100.08,43.73 105.66,38.15 125.49,38.15 126.25,37.38 127.57,37.38 128.06,37.86 130.09,37.86 130.93,37.02 141.07,37.02 v4(141.64,36.45)
  BOTTOM w0.203: R842.2 55.23,38.11 55.23,39.32 55.96,40.04 v2(64.07,40.04) ; v4(141.64,36.45) P801.C19
UNNAMED_7_CN400PAK_I27_N22: length 1.3
  TOP w0.203: v4(141.64,32.64) 141.67,32.67 R843.2
  BOTTOM w0.394: v4(141.64,32.64) P801.C22
UNNAMED_7_CN400PAK_I27_N23: length 1.4
  TOP w0.203: v4(140.37,32.64) 140.35,32.62 R844.2
  BOTTOM w0.394: P801.C23 v4(140.37,32.64)
UNNAMED_7_CN400PAK_I52_N2: length 1.5
  TOP w0.305: R801.2 133.69,58.37 v4(134.02,58.04)
  BOTTOM w0.203: v4(134.02,58.04) P801.H2
UNNAMED_7_CN400PAK_I52_N10: length 1.8
  TOP w0.394: R804.2 134.67,48.5 v4(135.29,47.88)
  BOTTOM w0.203: P801.H10 v4(135.29,47.88)
UNNAMED_7_CN400PAK_I52_N11: length 1.8
  TOP w0.394: R805.2 134.7,47.21 v4(135.29,46.61)
  BOTTOM w0.203: v4(135.29,46.61) P801.H11
UNNAMED_7_CN400PAK_I52_N13: length 1.5
  TOP w0.394: R806.2 v4(134.02,44.07)
  BOTTOM w0.203: v4(134.02,44.07) P801.H13
UNNAMED_7_CN400PAK_I52_N14: length 1.5
  TOP w0.394: R807.2 v4(135.29,44.07)
  BOTTOM w0.203: P801.H14 v4(135.29,44.07)
UNNAMED_7_CN400PAK_I52_N16: length 1.7
  TOP w0.203: v4(134.02,41.53) 134.02,41.15 R836.2
  BOTTOM w0.203: P801.H16 v4(134.02,41.53)
UNNAMED_7_CN400PAK_I52_N17: length 95.2
  L5_SIG w0.114: v4(134.02,40.26) 134.02,40.27 134.62,40.87 136.53,40.87 136.72,41.07 136.76,41.07 137.03,41.34 137.03,41.37 137.16,41.51 137.16,44.17 135.19,46.15 135.1,46.15 134.83,46.42 134.83,46.51 132.77,48.56 130.44,48.56 129.36,49.64 127.12,49.64 124.65,52.11 117.29,52.11 116.4,53 106.3,53 104.4,51.09 102.87,51.09 98.78,47.01 87.98,47.01 87.82,47.16 78.43,47.16 75.88,44.62 74.49,44.62 68.39,38.52 v2(64.07,38.52)
  BOTTOM w0.203: v4(134.02,40.26) P801.H17
  BOTTOM w0.254: 59.57,37.37 62.92,37.37 v2(64.07,38.52)
UNNAMED_7_CN400PAK_I52_N19: length 1.3
  TOP w0.203: v4(134.02,37.72) 134,37.7 R808.2
  BOTTOM w0.394: v4(134.02,37.72) P801.H19
UNNAMED_7_CN400PAK_I52_N20: length 1.3
  TOP w0.203: R809.2 134,36.43 v4(134.02,36.45)
  BOTTOM w0.394: v4(134.02,36.45) P801.H20
UNNAMED_7_CN400PAK_I52_N22: length 1.5
  TOP w0.203: R810.2 134.97,32.96 v4(135.29,32.64)
  BOTTOM w0.203: v4(135.29,32.64) P801.H22
UNNAMED_7_CN400PAK_I52_N23: length 1.5
  TOP w0.203: R811.2 134.97,31.69 v4(135.29,31.37)
  BOTTOM w0.203: v4(135.29,31.37) P801.H23
UNNAMED_7_CN400PAK_I52_N25: length 1.2
  TOP w0.203: v4(134.02,30.1) 134,30.08 R812.2
  BOTTOM w0.394: v4(134.02,30.1) P801.H25
UNNAMED_7_CN400PAK_I52_N26: length 61.9
  TOP w0.203: v1(99.57,41.89) 95.38,46.08 91.64,46.08 89.92,44.36 R813.2
  L7_SIG w0.114: v4(134.02,28.83) 134.02,29.22 134.56,29.76 134.56,30.2 135.26,30.91 135.49,30.91 135.83,31.25 135.83,39.11 135.34,39.6 129.48,39.6 129.17,39.29 102.13,39.29 99.57,41.86 v1(99.57,41.89)
  BOTTOM w0.394: v4(134.02,28.83) P801.H26
UNNAMED_7_CN400PAK_I55_N6: length 1.3
  TOP w0.203: R818.2 136.46,52.81 v4(136.59,52.94)
  BOTTOM w0.203: P801.G6 136.59,52.94 v4(136.59,52.94)
UNNAMED_7_CN400PAK_I55_N7: length 1.3
  TOP w0.203: v4(136.59,51.67) 136.46,51.79 R819.2
  BOTTOM w0.203: v4(136.59,51.67) 136.59,51.67 P801.G7
UNNAMED_7_CN400PAK_I55_N9: length 1.3
  TOP w0.203: R820.2 136.59,49.13 v4(136.56,49.15)
  BOTTOM w0.203: P801.G9 v4(136.56,49.15)
UNNAMED_7_CN400PAK_I55_N10: length 1.3
  TOP w0.203: R821.2 136.59,47.86 v4(136.56,47.88)
  BOTTOM w0.203: P801.G10 v4(136.56,47.88)
UNNAMED_7_CN400PAK_I55_N12: length 1.6
  TOP w0.203: R845.2 135.43,45.48 v4(135.29,45.34)
  BOTTOM w0.203: P801.G12 v4(135.29,45.34)
UNNAMED_7_CN400PAK_I55_N15: length 1.2
  TOP w0.203: v4(136.56,41.53) 136.46,41.63 R830.2
  BOTTOM w0.203: P801.G15 v4(136.56,41.53)
UNNAMED_7_CN400PAK_I55_N16: length 1.2
  TOP w0.203: v4(135.29,41.53) 135.32,41.56 R831.2
  BOTTOM w0.203: P801.G16 v4(135.29,41.53)
UNNAMED_7_CN400PAK_I55_N18: length 1.3
  TOP w0.203: R822.2 136.31,37.98 v4(136.56,37.72)
  BOTTOM w0.394: v4(136.56,37.72) P801.G18
UNNAMED_7_CN400PAK_I55_N19: length 1.3
  TOP w0.203: R823.2 135.27,37.7 v4(135.29,37.72)
  BOTTOM w0.394: P801.G19 v4(135.29,37.72)
UNNAMED_7_CN400PAK_I55_N21: length 1.2
  TOP w0.203: v4(135.29,33.91) 135.26,33.95 R824.2
  BOTTOM w0.203: P801.G21 v4(135.29,33.91)
UNNAMED_7_CN400PAK_I55_N22: length 1.2
  TOP w0.203: v4(136.56,33.91) 136.53,33.95 R825.2
  BOTTOM w0.203: P801.G22 v4(136.56,33.91)
UNNAMED_7_CN400PAK_I55_N24: length 1.6
  TOP w0.203: R826.2 136.12,30.92 v4(136.56,31.37)
  BOTTOM w0.203: P801.G24 v4(136.56,31.37)
UNNAMED_7_CN400PAK_I55_N25: length 1.9
  TOP w0.203: v4(136.56,28.83) 136.28,29.11 136.09,29.11 135.98,29.22 R827.2
  BOTTOM w0.394: v4(136.56,28.83) P801.G25
UNNAMED_7_CN400PAK_I55_N27: length 1.4
  TOP w0.203: R828.2 134.92,27.19 v4(135.29,27.56)
  BOTTOM w0.203: P801.G27 v4(135.29,27.56)
UNNAMED_7_CN400PAK_I55_N28: length 1.4
  TOP w0.203: R829.2 134.97,25.97 v4(135.29,26.29)
  BOTTOM w0.203: P801.G28 v4(135.29,26.29)
UNNAMED_7_CN400PAK_I67_N1: length 4.5
  TOP w0.394: R848.2 135.12,62.02 136.56,60.58 v4(137.83,60.58)
  BOTTOM w0.394: P801.F1 v4(137.83,60.58)
UNNAMED_9_AD7291_I112_DCAP: length 2.7
  TOP w0.305: U703.8 45.73,10.59 45.35,10.21 44.46,10.21 44.21,9.96
  TOP w0.394: 44.21,9.96 C706.1
UNNAMED_9_AD7291_I112_VIN0: length 5.3
  TOP w0.305: U703.18 51.2,10.59 51.58,10.21 52.09,10.21 53.48,8.81 R715.1 R714.1
UNNAMED_9_AD7291_I112_VIN1: length 4.6
  TOP w0.305: R717.2 53.62,11.04 ; 53.62,11.04 53.58,11.09 U703.19 ; 53.62,11.04 R716.2
UNNAMED_9_AD7291_I112_VIN2: length 5.3
  TOP w0.305: R719.2 R718.2 53.48,13.39 52.09,11.99 51.19,11.99 50.79,11.59 U703.20
UNNAMED_9_AD7291_I112_VIN3: length 4.7
  TOP w0.305: R721.2 R720.2 51.56,15.22 49.52,13.18 U703.1
UNNAMED_9_AD7291_I112_VIN4: length 4
  TOP w0.254: R723.2 R722.2 49.47,14.14 49.02,13.68 49.02,12.62 U703.2
UNNAMED_9_AD7291_I112_VIN5: length 3.9
  TOP w0.305: U703.3 48.51,12.62 48.51,14.34 48.4,14.44 R725.2 R724.2
UNNAMED_9_AD7291_I112_VIN7: length 4.3
  TOP w0.305: R726.2 R727.2 46.29,14.76 47.52,13.53 U703.5
UNNAMED_9_AD7291_I112_VREF: length 2.3
  TOP w0.305: C705.1 45.01,11.22 45.6,11.22 45.74,11.09 U703.7
UNNAMED_9_CN20PV2_I59_N1: length 35.2
  TOP w0.203: v1(68.84,54.52) 68.07,55.28 65.03,55.28 61.85,58.46 60.71,58.46 60.2,58.97 P701.2 ; R702.1 v1(85.72,44.3)
  L10_SIG w0.114: v1(68.84,54.52) 68.84,54.4 70.87,52.36 70.87,48.93 72.51,47.29 77.73,47.29 80.72,44.3 v1(85.72,44.3)
UNNAMED_9_CN20PV2_I59_N2: length 33.7
  TOP w0.203: v1(60.2,45.51) 60.2,37.7 61.22,36.68 61.22,35.85 60.64,35.28 R704.1
  TOP w0.394: P701.4 v2(58.93,58.07)
  L10_SIG w0.114: v2(58.93,58.07) 57.9,59.09 55.82,59.09 54.61,57.89 54.61,55.8 57.66,52.75 57.66,48.05 59.05,46.65 59.06,46.65 60.2,45.51 v1(60.2,45.51)
UNNAMED_9_CN20PV2_I59_N3: length 45.7
  TOP w0.203: R705.1 88.82,45.02 v1(88.2,45.63)
  TOP w0.394: P701.6 v2(57.66,58.07)
  L10_SIG w0.114: v2(57.66,58.07) 57.27,58.46 56.14,58.46 55.76,58.08 55.76,57.06 56.9,55.92 61.47,55.92 62.23,55.16 69.09,55.16 71.5,52.74 71.5,49.57 73.15,47.92 79.01,47.92 81.3,45.63 v1(88.2,45.63)
UNNAMED_9_CN20PV2_I59_N4: length 51
  TOP w0.203: v2(87.51,46.65) 87.51,36.76 R706.1
  TOP w0.394: P701.8 v2(56.39,57.89)
  L10_SIG w0.114: v2(56.39,57.89) 56.77,57.51 57.66,57.51 58.52,56.65 59.58,56.65 62.03,59.09 65.79,59.09 68.26,56.62 73.98,56.62 76.58,54.01 78.88,54.01 79.89,53.01 79.89,51.92 81,50.81 81.62,50.81 82.27,50.16 82.27,49.54 85.16,46.65 v2(87.51,46.65)
UNNAMED_9_CN20PV2_I59_N8: length 61.3
  TOP w0.203: R707.1 88.72,35.92 88.15,35.35 86.87,35.35 84.95,37.27 84.95,47.97 85.99,49.01 v2(85.99,51.86)
  TOP w0.394: P701.16 v2(51.31,58.07)
  L10_SIG w0.114: v2(85.99,51.86) 84.46,53.39 82.29,53.39 78.49,57.19 75.44,57.19 71.76,60.87 70.36,60.87 70.23,60.75 53.99,60.75 v2(51.31,58.07)
UNNAMED_9_CN20PV2_I60_N6: length 4.1
  TOP w0.394: P701.11 53.85,65.93 TP702.1
UNNAMED_9_CN20PV2_I60_N7: length 3.7
  TOP w0.394: P701.13 52.58,67 TP701.1
UNNAMED_9_CN20PV2_I60_N9: length 2.4
  TOP w0.394: R701.2 P701.17
UNNAMED_10_CAP_I118_N1: length 17.2
  BOTTOM w0.394: J301.1 C301.1 R302.1
UNNAMED_10_CAP_I121_N1: length 3.6
  BOTTOM w0.203: T301.1 21.19,34.55 C303.1
  BOTTOM w0.394: 21.19,34.55 20,34.54 ; 20,34.54 R302.2 ; 20,34.54 C303.1
UNNAMED_10_CNBNC3P_I129_CNTR: length 3.9
  BOTTOM w0.394: J305.1 23.24,37.76 24.7,36.3 24.7,35.66 24.07,35.03 R304.1
UNNAMED_10_CNBNC3P_I130_CNTR: length 3.4
  BOTTOM w0.394: R305.1 24.13,32.68 24.13,31.03 J306.1
UNNAMED_11_ADP125_I130_ADJ: length 3.1
  TOP w0.254: R940.2 R939.1 50.34,2.64 U902.3
UNNAMED_11_ADP5054_I29_BST1: length 2
  TOP w0.394: v2(83.45,13.92) 83.46,13.91 84.23,13.91 C913.1
  BOTTOM w0.203: U901.32 v2(83.45,13.92)
UNNAMED_11_ADP5054_I29_BST2: length 2
  TOP w0.394: v2(83.56,11.92) 83.58,11.9 C915.2
  BOTTOM w0.254: U901.28 v2(83.56,11.92)
UNNAMED_11_ADP5054_I29_BST3: length 2
  TOP w0.394: C917.1 93.44,15.92 v2(92.4,15.92)
  BOTTOM w0.254: U901.1 v2(92.4,15.92)
UNNAMED_11_ADP5054_I29_BST4: length 1.7
  BOTTOM w0.254: C919.1 92.86,10.42 U901.12
UNNAMED_11_ADP5054_I29_COMP1: length 2.8
  BOTTOM w0.254: R904.2 87.62,19.06 86.74,18.18 86.74,17.39 86.75,17.38 U901.40
UNNAMED_11_ADP5054_I29_COMP2: length 2.2
  BOTTOM w0.254: R907.2 86.63,7.96 87.25,8.58 U901.20
UNNAMED_11_ADP5054_I29_COMP3: length 2.8
  BOTTOM w0.203: U901.47 90.25,17.13 90.27,17.15 90.27,17.19 90.94,17.86 90.94,19 R908.2
UNNAMED_11_ADP5054_I29_COMP4: length 2.1
  BOTTOM w0.254: R911.2 90,8.17 89.75,8.42 U901.15
UNNAMED_11_ADP5054_I29_DL1: length 5.4
  TOP w0.394: R918.2 81.58,11.52 82.31,11.52 v2(82.33,11.49)
  BOTTOM w0.203: U901.31 83.99,13.42 83.94,13.36 83.3,13.36 82.99,13.06 82.99,12.15 v2(82.33,11.49)
  BOTTOM w0.254: v2(82.33,11.49) 82.31,11.52 Q901.5
UNNAMED_11_ADP5054_I29_DL2: length 9.1
  TOP w0.394: v2(78.55,11.52) 81.17,14.14 82.29,14.14 ; R919.2 82.29,14.14 ; 82.29,14.14 82.43,14.01 83.55,12.89 v2(83.55,12.76)
  BOTTOM w0.203: U901.29 83.9,12.42 v2(83.55,12.76)
  BOTTOM w0.254: Q901.2 v2(78.55,11.52)
UNNAMED_11_ADP5054_I29_EN1: length 48.1
  L5_SIG w0.394: v2(90.36,8.7) 90.36,9.25 90.81,9.7 92.21,9.7 94.5,11.98 94.5,17.83 93.1,19.22 91.58,19.22 91.07,18.72 91.07,18.21 90.18,17.32 86.69,17.32 v2(85.59,18.43) 84.92,19.09 82.68,19.09 81.23,17.64 72.34,17.64 69.13,20.85 P902.2
  BOTTOM w0.254: U901.14 90.25,8.81 v2(90.36,8.7) 91.03,8.03 R906.1 ; U901.39 86.25,17.76 v2(85.59,18.43) R905.2 C911.2
UNNAMED_11_ADP5054_I29_EN2: length 51.7
  TOP w0.305: P902.1 73.33,19.83 R902.2
  TOP w0.394: v2(86.65,8.8) 86.87,8.59 R903.1
  L5_SIG w0.394: P902.1 69.62,23.55 65.8,23.55 63.64,21.38 63.64,17.65 64.58,16.71 66.92,16.71 69.61,14.02 77.1,14.02 80.78,10.33 80.78,9.87 83.12,7.53 85.84,7.53 86.65,8.34 v2(86.65,8.8)
  BOTTOM w0.254: U901.21 86.75,8.9 v2(86.65,8.8)
UNNAMED_11_ADP5054_I29_EN3: length 35.8
  L5_SIG w0.394: v2(91.95,18.33) 91.95,17.44 91.07,16.56 85.73,16.56 84.75,17.54 82.43,17.54 81.45,16.56 71.53,16.56 P902.3
  BOTTOM w0.203: U901.48 90.75,16.74 90.94,16.94 90.94,17.06
  BOTTOM w0.254: P902.3 66.6,21.5 R912.1
  BOTTOM w0.394: 90.94,17.06 91.95,18.07 v2(91.95,18.33) R909.2 R910.1 C912.2
UNNAMED_11_ADP5054_I29_FB1: length 38.2
  TOP w0.394: v2(74.41,21.3) 74.41,21.93 76.21,23.74 82.35,23.74 84.08,22.01 84.08,20.27 84.3,20.04 ; 84.3,20.04 R916.1 ; 84.3,20.04 85.94,20.04 R914.1 87.72,18.54 87.72,18.38 87.72,18.38 v2(87.72,18.33)
  L5_SIG w0.394: v2(87.72,18.33) 87.72,18.33 87.56,18.33 85.78,20.11 75.59,20.11 v2(74.41,21.3)
  BOTTOM w0.254: U901.41 87.25,17.7 87.72,18.18 v2(87.72,18.33)
  BOTTOM w0.508: 74.41,20.14 74.41,19.47 74.05,19.11 R917.1 ; 74.41,20.14 R915.1 74.41,20.42 ; 74.41,20.14 74.41,20.42 ; 74.41,20.42 v2(74.41,21.3)
UNNAMED_11_ADP5054_I29_FB2: length 21.9
  TOP w0.394: 86.59,6.39 87.49,6.39 v2(87.59,6.49) ; 86.59,6.39 R923.1 ; 86.59,6.39 R920.2
  BOTTOM w0.203: v2(87.59,6.49) 87.59,7.73 87.75,7.89 U901.19
  BOTTOM w0.508: R922.1 75.81,3.91 R921.1 76.06,3.09 86.87,3.09 87.52,3.73 87.52,6.41 v2(87.59,6.49)
UNNAMED_11_ADP5054_I29_FB3: length 13.6
  TOP w0.394: R927.1 96.29,20.17 ; 96.29,20.17 94.48,20.17 ; 96.29,20.17 96.29,21.15 v2(96.55,21.4) ; v2(90.28,18.43) 92.02,20.17 94.48,20.17 ; 94.48,20.17 94.51,20.21 R924.2
  BOTTOM w0.203: U901.46 89.75,17.38 90.28,17.92 v2(90.28,18.43)
  BOTTOM w0.394: R925.1 97.45,21.4
  BOTTOM w0.508: R926.1 96.91,20.08 97.45,20.61 97.45,21.4 v2(96.55,21.4)
UNNAMED_11_ADP5054_I29_FB4: length 20.3
  TOP w0.394: R931.1 92.29,7.75 90.79,7.75 ; v2(89.17,7.73) 89.18,7.75 90.79,7.75 ; 90.79,7.75 R928.2
  BOTTOM w0.203: U901.16 89.25,7.82 v2(89.17,7.73)
  BOTTOM w0.254: v2(89.17,7.73) 89.17,5.78 89.09,5.7
  BOTTOM w0.508: 89.09,5.7 89.09,3.62 89.62,3.09 95.63,3.09 97.16,4.61 R929.1 97.55,5.05 R930.1
UNNAMED_11_ADP5054_I29_PWRGD: length 31.6
  L5_SIG w0.508: v2(88.53,6.72) 87.39,7.86 87.39,9.17 86.73,9.83 84.59,9.83 83.63,10.78 81.6,10.78 77.18,15.21 71.05,15.21 67.54,18.72 v2(66.56,18.72)
  BOTTOM w0.203: v2(88.53,6.72) 88.53,8.09 88.75,8.31 U901.17
  BOTTOM w0.394: v2(66.56,18.72) R912.2
UNNAMED_11_ADP5054_I29_RT: length 2.8
  BOTTOM w0.203: R913.1 88.63,19.07 88.28,18.72 88.28,18.1 88.28,18.1 88.28,18.02 87.75,17.49 U901.42
UNNAMED_11_ADP5054_I29_SW11: length 6.5
  TOP w0.394: C913.2 84.37,15.18 83.53,15.18 v2(83.32,15.38) v2(83.32,14.74)
  BOTTOM w0.254: U901.33 83.8,14.42 83.48,14.74 v2(83.32,14.74) ; U901.35 83.36,15.42 v2(83.32,15.38) ; Q901.PAD2 80,11.98 79.81,12.17 Q901.3 79.6,12.95 79.84,13.2
UNNAMED_11_ADP5054_I29_SW21: length 6.3
  TOP w0.394: v2(82.64,10.07) v2(82.64,9.41) 82.97,9.74 83.58,9.74 C915.1
  BOTTOM w0.254: Q901.6 81.42,10.15 ; Q901.6 81.11,10.87 80.93,11.05 Q901.PAD1 ; Q901.6 82.17,10.87 82.38,10.66 ; U901.27 83.89,11.42 83.58,11.11 ; U901.25 83.86,10.42
UNNAMED_11_ADP5054_I29_SW31: length 4.8
  TOP w0.394: C917.2 93.45,14.2 v2(93.76,13.88) v2(93.13,13.88)
  BOTTOM w0.254: U901.4 92.87,14.42 ; v2(93.13,13.88) 93.09,13.92 U901.5
UNNAMED_11_ADP5054_I29_SW41: length 3.3
  BOTTOM w0.254: U901.9 92.83,11.92 93.07,11.68 ; 93.07,11.68 C919.2 ; 93.07,11.68 93.08,11.68 ; 92.9,12.05 92.53,12.42 U901.8
UNNAMED_11_ADP5054_I29_VDD: length 2.9
  TOP w0.394: C903.2 89.22,18.66 v2(88.89,18.33)
  BOTTOM w0.203: v2(88.89,18.33) 88.89,18 88.25,17.36 U901.43
UNNAMED_11_CAP_I25_N2: length 1
  BOTTOM w0.394: R911.1 C910.2
UNNAMED_11_CAP_I27_N2: length 1
  BOTTOM w0.394: C908.2 R908.1
UNNAMED_11_CAP_I30_N2: length 1
  BOTTOM w0.381: C906.2 R907.1
UNNAMED_11_CAP_I32_N2: length 1
  BOTTOM w0.381: R904.1 C904.2
UNNAMED_11_CAP_I54_N1: length 1.4
  BOTTOM w0.508: R929.2 98.54,5.03 C920.1
UNNAMED_11_CAP_I55_N1: length 2.4
  BOTTOM w0.394: R925.2 98.72,21.4
  BOTTOM w0.508: 98.72,21.4 98.72,20.61 99.2,20.13 C918.1
UNNAMED_11_CAP_I56_N1: length 1.3
  BOTTOM w0.508: C916.1 74.31,3.85 R921.2
UNNAMED_11_CAP_I59_N1: length 2.2
  BOTTOM w0.508: R915.2 75.68,20.14 75.68,19.44 76.09,19.04 C914.1
UNNAMED_11_CAP_I80_N2: length 2.2
  BOTTOM w0.762: R937.1 C931.2
UNNAMED_11_CAP_I84_N2: length 3.5
  BOTTOM w0.762: C929.2 106.75,17.89 108.45,16.2 R934.1
UNNAMED_11_CAP_I93_N2: length 2.1
  BOTTOM w0.762: R933.1 68.45,9.99 C927.2
UNNAMED_11_CAP_I103_N2: length 2.1
  BOTTOM w0.762: C924.2 68.02,18.35 R932.1
UNNAMED_11_CN2P_I1_N1: length 5.3
  TOP w0.508: P901.1 112.53,9.57 ; P901.1 109.86,9.57 ; P901.1 111.2,8.24 ; P901.1 111.2,10.91
UNNAMED_11_DIOLED_I8_N: length 2
  TOP w0.203: R901.2 122.49,1.51 122.27,1.72 DS901.C
UNNAMED_11_DIOLED_I179_P: length 2.1
  TOP w0.508: R935.2 DS902.A
VCXO_CON: length 5.5
  BOTTOM w0.394: Y401.1 Y402.1 C406.1 123.61,63.8 123.62,63.82 R407.2
VCXO_CTRL: length 42
  L5_SIG w0.114: v2(126.07,63.82) 123.22,63.82 121.22,61.83 101.16,61.83 94.69,55.35 90.35,55.35 v2(89.88,54.89)
  BOTTOM w0.254: v2(89.88,54.89) 90.04,55.05 90.04,55.43 U401.8
  BOTTOM w0.394: v2(126.07,63.82) R407.1
VCXO_EN: length 5.4
  BOTTOM w0.394: Y401.2 Y402.2 122.22,61.26 122.29,61.2 R409.2 R408.2
VCXO_IN+: length 5.5
  BOTTOM w0.203: C409.2 88.76,50.65 R416.1 88.47,50.97 88.47,55.01 88.54,55.08 88.54,55.37 U401.11
VCXO_IN-: length 5.5
  BOTTOM w0.203: U401.12 88.04,55.3 88.04,55.08 88.11,55.01 88.11,51.02 R415.1 87.72,50.67 87.73,50.67 R411.2
VCXO_OUT+: length 4.5
  BOTTOM w0.203: Y401.4 Y402.4 111.94,58.72 111.22,59.45 R410.1
VCXO_OUT-: length 4.6
  BOTTOM w0.203: R417.1 111.24,60.48 112.03,61.26 Y402.5 Y401.5

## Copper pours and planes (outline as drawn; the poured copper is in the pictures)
AGND on TOP: 0,0 0,21.11 0.62,21.11 0.83,21.5 0.82,23.71 0.62,24.1 0,24.1 0,44.99 0.62,44.99 0.83,45.37 0.82,47.59 0.62,47.97 0,47.98 0,69.09 148.44,69.09 148.44,0 ; 11 cut-outs
AGND on BOTTOM: 0,0 0,33.05 0.58,33.05 0.78,33.44 0.78,35.65 0.58,36.03 0,36.04 0,69.09 148.44,69.09 148.44,0 ; 14 cut-outs
AGND on L2_GND: 0,0 0,69.09 148.44,69.09 148.44,0 ; 4 cut-outs
AGND on L3_PWR: 0,0 0,69.09 148.44,69.09 148.44,0 ; 3 cut-outs
AGND on L4_GND: 0,0 0,69.09 148.44,69.09 148.44,0 ; 2 cut-outs
AGND on L5_SIG: 0,0 0,69.09 148.44,69.09 148.44,0 ; 36 cut-outs
AGND on L6_GND: 0,0 0,69.09 148.44,69.09 148.44,0 ; 2 cut-outs
AGND on L7_SIG: 0,0 0,69.09 148.44,69.09 148.44,0 ; 28 cut-outs
AGND on L8_SIG: 0,0 0,69.09 148.44,69.09 148.44,0 ; 37 cut-outs
AGND on L9_GND, L11_GND, L13_GND: 0,0 0,69.09 148.44,69.09 148.44,0
AGND on L10_SIG: 0,0 0,69.09 148.44,69.09 148.44,0 ; 3 cut-outs
AGND on L12_PWR: 0,0 0,69.09 148.44,69.09 148.44,0 ; 1 cut-out
VDD1P3_DIG on BOTTOM: 54.1,24.3 51.95,24.3 51.69,24.04 51.69,21.76 52.33,21.12 53.6,21.12 54.49,22.01 54.49,23.92
VDD1P3_DIG on BOTTOM: 71,8.41 71,6.14 70.75,5.89 65.78,5.89 62.99,8.68 61.09,8.68 60.96,8.8 60.96,10.07 61.09,10.2 63.63,10.2 64.39,10.96 66.17,10.96 66.68,10.45 66.68,9.06 66.93,8.8 70.61,8.8
VDD1P3_DIG on L5_SIG: 71,8.81 71,6.02 70.88,5.89 66.16,5.89 63.5,8.55 63.5,9.95 64.52,10.96 66.04,10.96 68.07,8.94 70.88,8.94
VDD1P3_DIG on L8_SIG: 67.73,5.84 70.98,5.84 71.08,5.94 71.08,8.35 68.46,10.97 63.64,10.97 63.13,10.46 63.13,8.3 64.27,7.16 66.4,7.16
VDD_IF_LDO on TOP: 58.05,3.13 58.12,3.21 59.98,3.21 60.21,3.44 60.21,5.63 59.57,6.27 56.78,6.27 56.78,4.75 56.31,4.28 55.89,4.28 55.84,4.23 55.84,3.27 55.98,3.13
VDD_INTERFACE on TOP: 50.75,3.21 49.92,3.22 49.41,2.71 49.41,1.57 48.9,1.06 45.86,1.06 45.35,1.57 45.35,3.35 45.98,3.98 47.38,3.98 49.54,6.14 52.71,6.14 52.84,6.02 52.84,4.78 52.81,4.78 52.81,3.28 52.71,3.18 51.62,3.18 51.49,3.31 50.78,3.31 50.75,3.28
VDD_INTERFACE on L12_PWR: 75.7,22.14 63.76,10.21 54.89,10.21 51.68,7.03 49.41,7.03 45.47,3.09 45.47,1.94 46.74,0.67 69.22,0.67 80.91,12.37 80.91,18.21 89.03,26.33 128.91,26.33 138.19,35.61 138.19,40.31 137.8,40.69 103.51,40.69 98.82,45.39 77.61,45.39 75.7,43.48
VDDA1P3_ANLG on TOP: 59.31,17.06 57.53,15.28 57.53,14.14 58.3,13.37 63.5,13.37 64.14,14.01 71,14.01 71.38,14.39 71.38,16.42 71,16.8 63.5,16.8 63.25,17.06
VDDA1P3_ANLG on BOTTOM: 67.68,13.36 58.04,13.38 55.76,15.66 55.76,18.07 55.88,18.2 60.45,18.2 61.6,17.06 70.25,17.06 70.45,16.86 70.45,16.13
VDDA1P3_ANLG on BOTTOM: 50.71,19.44 50.55,19.6 49.53,19.6 49.31,19.38 49.31,18.29 49.53,18.07 50.55,18.07 50.71,18.23
VDDA1P3_ANLG on L8_SIG: 58.18,16.94 65.78,16.94 66.4,16.31 66.4,14.63 65.8,14.02 63.49,14.02 62.86,13.37 58.17,13.37 57.28,14.26 57.28,16.04
VDDA1P3_ANLG on L12_PWR: 6.48,14.91 12.73,8.66 50.02,8.66 53.85,12.49 63.38,12.49 65.92,15.03 65.92,15.91 62.35,19.48 54.75,19.48 53.98,18.71 45.6,18.71 45.47,18.58 34.17,18.58 30.99,15.41 28.2,15.41 18.93,24.67 18.93,35.35 16.39,37.89 16.39,40.17 18.54,42.33 18.54,54.64 20.8,56.94 21.59,56.94 21.97,57.32 21.97,60.11 19.81,62.27 19.31,62.27 17.91,60.87 17.91,60.11 9.4,51.61 9.41,50.97 6.48,48.05 ; 1 cut-out
VDDA1P3_RF_LO on BOTTOM: 8.26,45 8.77,44.49 9.78,44.49 16.39,37.89 17.27,37.89 17.53,38.14 17.53,39.79 10.04,47.28 9.91,47.28 8.26,45.63
VDDA1P3_RF_SYNTH on BOTTOM: 26.55,58.21 23.75,58.21 22.99,58.97 22.99,61.63 23.12,61.76 24.13,61.76 24.51,62.14 24.51,62.52 24.77,62.78 27.56,62.78 27.69,62.65 27.69,61.13 27.43,60.87 26.8,60.87 26.8,58.46
VDDA1P3_RX on L12_PWR: 26.67,25.82 26.67,28.36 26.55,28.49 26.55,31.15 27.69,32.3 29.72,32.3 30.36,31.66 30.36,30.9 30.1,30.65 29.85,30.65 29.47,31.03 28.83,31.03 28.32,30.52 28.32,26.96 27.05,25.69 26.8,25.69
VDDA1P3_SER on L3_PWR: 38.36,38.65 36.45,38.65 36.2,38.9 36.2,39.16 36.96,39.92 39.63,39.92 39.88,39.66 39.88,33.95 39.75,33.82 38.74,33.82 38.61,33.95 38.61,38.39
VDDA1P8_AN on TOP: 103.13,4.99 99.44,4.99 98.94,4.48 98.94,1.61 100.1,0.45 101.88,0.45 101.88,2.35 103.25,3.72 103.25,4.87
VDDA1P8_AN on L3_PWR: 81.42,7.29 104.28,7.29 106.03,5.53 106.03,2.37 104.59,0.94 49.94,0.94 43.34,7.54 19.19,7.54 14.54,12.19 14.54,38.63 17.86,41.95 26.7,41.95 26.7,37.62 28.08,36.24 28.08,16.18 30.32,13.93 30.99,13.93 34.04,16.98 46.81,16.98 48.12,15.68 55.8,15.68 61.65,9.83 78.88,9.83
VDDA_1P8 on TOP: 105.03,5.88 103.25,5.88 103.13,5.75 103.13,5.37 103.63,4.87 103.63,2.83 103.76,2.71 104.27,2.71 104.65,3.09 107.7,3.09 108.08,3.47 108.08,5.75 107.7,6.14 105.29,6.14
VDDA_1P8 on BOTTOM: 105.03,5.88 103.25,5.88 103.13,5.75 103.13,5.37 103.51,4.99 103.51,2.45 103.8,2.16 104.86,2.16 105.79,3.09 107.7,3.09 109.48,4.87 109.48,8.04 109.35,8.17 107.7,8.17 107.57,8.04 107.57,6.9 107.32,6.64 105.79,6.64
VDDA_3P3 on TOP: 56.78,7.16 56.78,8.43 57.44,9.09 59.55,9.09 59.83,8.81 59.83,7.29 59.57,7.03 56.91,7.03
